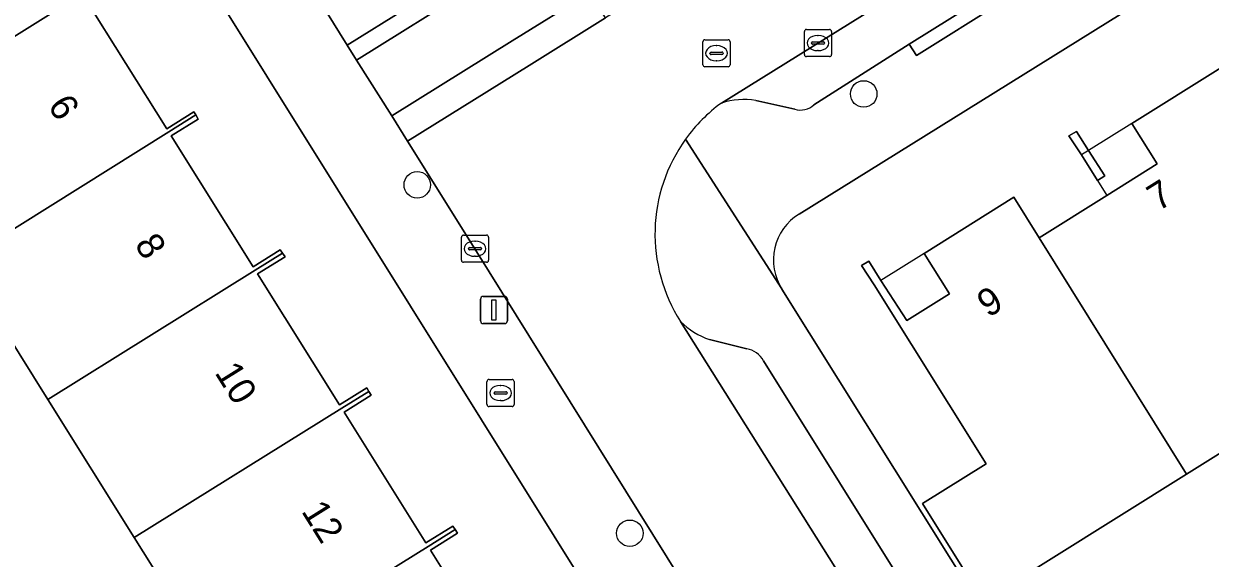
# Model space of a CAD drawing. Extents: x 158835 to 160077, y 386387 to 387778.
# Drawn here: x 159103.26 to 159146.99, y 387136.96 to 387156.67 of the extents above; entities that cross this region are included whole.
import ezdxf

# ---------------------------------------------------------------- set-up
doc = ezdxf.new("R2010")
doc.units = 0
for name, color, linetype in [('IMGEO_Boom', 7, 'Continuous'), ('IMGEO_Brandkraan', 7, 'Continuous'), ('IMGEO_Erf', 7, 'Continuous'), ('IMGEO_Kolk', 7, 'Continuous'), ('IMGEO_Lichtmast', 7, 'Continuous'), ('IMGEO_Pand', 7, 'Continuous'), ('IMGEO_Pand_nummerreeks', 7, 'Continuous'), ('IMGEO_Pand_overbouw', 7, 'Continuous'), ('IMGEO_Parkeervlak_open', 7, 'Continuous'), ('IMGEO_Rijbaan_lokaal_open', 7, 'Continuous'), ('IMGEO_Rioolput', 7, 'Continuous'), ('IMGEO_Voetpad_open', 7, 'Continuous')]:
    doc.layers.add(name, color=color, linetype=linetype)

msp = doc.modelspace()

# ---------------------------------------------------------------- linework, layer by layer
at = {"layer": 'IMGEO_Boom'}
for centre in [(159134.213, 387154.078), (159117.763, 387150.726), (159125.594, 387137.881)]:
    msp.add_circle(centre, 0.489, dxfattribs=at)
at = {"layer": 'IMGEO_Brandkraan'}
for p, q in [((159120.332, 387142.626), (159120.332, 387143.478)), ((159120.407, 387143.552), (159121.259, 387143.552)), ((159120.82, 387143.332), (159120.845, 387143.332)), ((159121.333, 387143.478), (159121.333, 387142.626)), ((159120.591, 387143.046), (159120.591, 387143.058)), ((159121.029, 387143.009), (159120.631, 387143.009)), ((159120.634, 387143.095), (159121.032, 387143.095)), ((159120.843, 387142.772), (159120.818, 387142.772)), ((159121.075, 387143.058), (159121.075, 387143.046)), ((159121.259, 387142.552), (159120.407, 387142.552))]:
    msp.add_line(p, q, dxfattribs=at)
for points in [[(159120.332, 387142.626), (159120.332, 387143.478)], [(159120.407, 387143.552), (159121.259, 387143.552)], [(159121.333, 387143.478), (159121.333, 387142.626)], [(159121.259, 387142.552), (159120.407, 387142.552)]]:
    msp.add_lwpolyline(points, dxfattribs=at)
for centre, radius, start, end in [((159120.409, 387143.476), 0.0765, 91.552, 178.448), ((159120.409, 387143.476), 0.0765, 91.552, 178.448), ((159121.257, 387143.476), 0.0765, 1.552, 88.448), ((159121.257, 387143.476), 0.0765, 1.552, 88.448), ((159120.631, 387143.055), 0.0403, 85.8775, 175.7526), ((159120.628, 387143.045), 0.0366, 178.938, 274.7102), ((159121.032, 387143.052), 0.043, 264.8664, 352.4533), ((159121.036, 387143.057), 0.0386, 1.7309, 96.639), ((159120.409, 387142.628), 0.0765, 181.552, 268.448), ((159120.409, 387142.628), 0.0765, 181.552, 268.448), ((159121.257, 387142.628), 0.0765, 271.552, 358.448), ((159121.257, 387142.628), 0.0765, 271.552, 358.448)]:
    msp.add_arc(centre, radius, start, end, dxfattribs=at)
for centre, major_axis, ratio, start_param, end_param in [((159120.819, 387143.052), (-0.387, 0.002), 0.722429, 4.712389, 7.853982), ((159120.844, 387143.052), (-0.39, 0.002), 0.717154, 1.570796, 4.712389)]:
    msp.add_ellipse(centre, major_axis=major_axis, ratio=ratio, start_param=start_param, end_param=end_param, dxfattribs=at)
at = {"layer": 'IMGEO_Erf'}
for points in [[(159192.812, 387154.528), (159184.858, 387169.495), (159180.565, 387177.574), (159180.465, 387177.724), (159180.352, 387177.865), (159180.227, 387177.995), (159180.091, 387178.113), (159179.944, 387178.219), (159179.789, 387178.311), (159179.627, 387178.389), (159179.458, 387178.452), (159179.284, 387178.5), (159179.106, 387178.532), (159178.926, 387178.548), (159178.746, 387178.548), (159178.566, 387178.532), (159178.388, 387178.5), (159178.214, 387178.452), (159178.045, 387178.389), (159177.883, 387178.311), (159177.794, 387178.26), (159131.832, 387149.649)], [(159128.1, 387129.289), (159098.935, 387175.998)], [(159105.515, 387157.619), (159108.532, 387152.795), (159109.533, 387153.421), (159109.601, 387153.308), (159109.693, 387153.153), (159108.697, 387152.53), (159111.713, 387147.708), (159112.714, 387148.334), (159112.799, 387148.209), (159112.89, 387148.073), (159111.879, 387147.441), (159114.899, 387142.611), (159115.903, 387143.239), (159115.98, 387143.113), (159116.067, 387142.972), (159115.065, 387142.346), (159118.079, 387137.527), (159119.072, 387138.148), (159119.159, 387138.018), (159119.247, 387137.885), (159118.246, 387137.259), (159121.256, 387132.446)], [(159153.734, 387144.832), (159146.108, 387140.062), (159138.627, 387135.383), (159136.383, 387138.973), (159138.73, 387140.444), (159134.594, 387147.043), (159134.13, 387147.748), (159134.4, 387147.914), (159134.847, 387147.201), (159135.801, 387145.722), (159137.374, 387146.707), (159136.44, 387148.199), (159139.747, 387150.271), (159140.678, 387148.777), (159143.174, 387150.339), (159145.023, 387151.496), (159144.089, 387152.989), (159147.369, 387155.042)], [(159102.591, 387130.021), (159103.629, 387128.333), (159102.891, 387127.877), (159105.538, 387123.606), (159102.83, 387121.872), (159104.491, 387119.253), (159107.123, 387120.891), (159109.245, 387117.494), (159116.968, 387122.325), (159113.699, 387127.551), (159110.519, 387132.633), (159107.334, 387137.724), (159104.149, 387142.815), (159100.965, 387147.905)], [(159131.202, 387146.887), (159138.432, 387135.312), (159143.549, 387127.119), (159158.165, 387103.724), (159222.278, 387001.075)]]:
    msp.add_lwpolyline(points, dxfattribs=at)
msp.add_lwpolyline([(159143.102, 387151.057), (159142.831, 387150.887), (159142.24, 387151.831), (159141.777, 387152.54), (159142.052, 387152.699), (159142.495, 387151.991)], close=True, dxfattribs=at)
msp.add_arc((159132.858, 387147.962), 1.974, 121.3088, 212.993, dxfattribs=at)
at = {"layer": 'IMGEO_Kolk'}
for p, q in [((159132.028, 387155.529), (159132.028, 387156.381)), ((159132.103, 387156.455), (159132.955, 387156.455)), ((159133.029, 387156.381), (159133.029, 387155.529)), ((159132.287, 387155.949), (159132.287, 387155.961)), ((159132.725, 387155.912), (159132.327, 387155.912)), ((159132.33, 387155.998), (159132.728, 387155.998)), ((159132.516, 387156.235), (159132.541, 387156.235)), ((159132.771, 387155.961), (159132.771, 387155.949)), ((159132.955, 387155.455), (159132.103, 387155.455)), ((159132.539, 387155.675), (159132.514, 387155.675)), ((159119.465, 387148.872), (159120.317, 387148.872)), ((159119.39, 387147.946), (159119.39, 387148.798)), ((159119.692, 387148.415), (159120.09, 387148.415)), ((159119.878, 387148.652), (159119.903, 387148.652)), ((159120.391, 387148.798), (159120.391, 387147.946)), ((159119.649, 387148.366), (159119.649, 387148.378)), ((159120.087, 387148.329), (159119.689, 387148.329)), ((159119.901, 387148.092), (159119.876, 387148.092)), ((159120.133, 387148.378), (159120.133, 387148.366)), ((159120.317, 387147.872), (159119.465, 387147.872))]:
    msp.add_line(p, q, dxfattribs=at)
for points in [[(159132.028, 387155.529), (159132.028, 387156.381)], [(159132.103, 387156.455), (159132.955, 387156.455)], [(159133.029, 387156.381), (159133.029, 387155.529)], [(159132.955, 387155.455), (159132.103, 387155.455)], [(159119.465, 387148.872), (159120.317, 387148.872)], [(159119.39, 387147.946), (159119.39, 387148.798)], [(159120.391, 387148.798), (159120.391, 387147.946)], [(159120.317, 387147.872), (159119.465, 387147.872)]]:
    msp.add_lwpolyline(points, dxfattribs=at)
for centre, radius, start, end in [((159132.105, 387156.379), 0.0765, 91.552, 178.448), ((159132.105, 387156.379), 0.0765, 91.552, 178.448), ((159132.953, 387156.379), 0.0765, 1.552, 88.448), ((159132.953, 387156.379), 0.0765, 1.552, 88.448), ((159132.327, 387155.958), 0.0403, 85.8775, 175.7526), ((159132.324, 387155.948), 0.0366, 178.938, 274.7102), ((159132.728, 387155.955), 0.043, 264.8664, 352.4533), ((159132.732, 387155.96), 0.0386, 1.7309, 96.639), ((159132.105, 387155.531), 0.0765, 181.552, 268.448), ((159132.105, 387155.531), 0.0765, 181.552, 268.448), ((159132.953, 387155.531), 0.0765, 271.552, 358.448), ((159132.953, 387155.531), 0.0765, 271.552, 358.448), ((159119.467, 387148.796), 0.0765, 91.552, 178.448), ((159119.467, 387148.796), 0.0765, 91.552, 178.448), ((159120.315, 387148.796), 0.0765, 1.552, 88.448), ((159120.315, 387148.796), 0.0765, 1.552, 88.448), ((159119.689, 387148.375), 0.0403, 85.8775, 175.7526), ((159120.094, 387148.377), 0.0386, 1.7309, 96.639), ((159119.467, 387147.948), 0.0765, 181.552, 268.448), ((159119.467, 387147.948), 0.0765, 181.552, 268.448), ((159119.686, 387148.365), 0.0366, 178.938, 274.7102), ((159120.09, 387148.372), 0.043, 264.8664, 352.4533), ((159120.315, 387147.948), 0.0765, 271.552, 358.448), ((159120.315, 387147.948), 0.0765, 271.552, 358.448)]:
    msp.add_arc(centre, radius, start, end, dxfattribs=at)
for centre, major_axis, ratio, start_param, end_param in [((159132.515, 387155.955), (-0.387, 0.002), 0.722429, 4.712389, 7.853982), ((159132.54, 387155.955), (-0.39, 0.002), 0.717154, 1.570796, 4.712389), ((159119.877, 387148.372), (-0.387, 0.002), 0.722429, 4.712389, 7.853982), ((159119.902, 387148.372), (-0.39, 0.002), 0.717154, 1.570796, 4.712389)]:
    msp.add_ellipse(centre, major_axis=major_axis, ratio=ratio, start_param=start_param, end_param=end_param, dxfattribs=at)
at = {"layer": 'IMGEO_Lichtmast'}
for p, q in [((159120.094, 387145.713), (159120.094, 387146.513)), ((159120.094, 387146.513), (159120.094, 387145.713)), ((159120.194, 387146.613), (159120.984, 387146.613)), ((159120.984, 387146.613), (159120.194, 387146.613)), ((159121.084, 387146.513), (159121.084, 387145.713)), ((159121.084, 387145.713), (159121.084, 387146.513)), ((159120.984, 387145.613), (159120.194, 387145.613)), ((159120.194, 387145.613), (159120.984, 387145.613))]:
    msp.add_line(p, q, dxfattribs=at)
msp.add_lwpolyline([(159120.514, 387146.488), (159120.664, 387146.488), (159120.664, 387145.738), (159120.514, 387145.738), (159120.514, 387146.488)], dxfattribs=at)
for centre, start, end in [((159120.194, 387146.513), 90, 180), ((159120.194, 387146.513), 90, 180), ((159120.984, 387146.513), 0, 90), ((159120.984, 387146.513), 360, 90), ((159120.194, 387145.713), 180, 270), ((159120.194, 387145.713), 180, 270), ((159120.984, 387145.713), 270, 0), ((159120.984, 387145.713), 270, 0)]:
    msp.add_arc(centre, 0.1, start, end, dxfattribs=at)
at = {"layer": 'IMGEO_Pand'}
for points in [[(159102.237, 387162.861), (159094.601, 387158.079), (159097.78, 387152.996), (159105.417, 387157.775), (159106.421, 387158.403), (159106.353, 387158.513), (159105.348, 387157.885), (159102.329, 387162.713), (159103.328, 387163.337), (159103.238, 387163.488)], [(159109.601, 387153.308), (159109.533, 387153.421), (159108.532, 387152.795), (159105.515, 387157.619), (159106.518, 387158.246), (159106.421, 387158.403), (159105.417, 387157.775), (159097.78, 387152.996), (159100.965, 387147.905), (159108.602, 387152.683)], [(159148.301, 387153.547), (159147.369, 387155.042), (159144.089, 387152.989), (159145.023, 387151.496), (159143.174, 387150.339), (159140.678, 387148.777), (159146.108, 387140.062), (159153.734, 387144.832)], [(159108.602, 387152.683), (159100.965, 387147.905), (159104.149, 387142.815), (159111.792, 387147.581), (159112.799, 387148.209), (159112.714, 387148.334), (159111.713, 387147.708), (159108.697, 387152.53), (159109.693, 387153.153), (159109.601, 387153.308)], [(159142.495, 387151.991), (159142.052, 387152.699), (159141.777, 387152.54), (159142.24, 387151.831), (159142.831, 387150.887), (159143.102, 387151.057)], [(159140.678, 387148.777), (159139.747, 387150.271), (159136.44, 387148.199), (159137.374, 387146.707), (159135.801, 387145.722), (159134.847, 387147.201), (159134.4, 387147.914), (159134.13, 387147.748), (159134.594, 387147.043), (159138.73, 387140.444), (159136.383, 387138.973), (159138.627, 387135.383), (159146.108, 387140.062)], [(159115.98, 387143.113), (159115.903, 387143.239), (159114.899, 387142.611), (159111.879, 387147.441), (159112.89, 387148.073), (159112.799, 387148.209), (159111.792, 387147.581), (159104.149, 387142.815), (159107.334, 387137.724), (159114.977, 387142.488)], [(159114.977, 387142.488), (159107.334, 387137.724), (159110.519, 387132.633), (159118.161, 387137.396), (159119.159, 387138.018), (159119.072, 387138.148), (159118.079, 387137.527), (159115.065, 387142.346), (159116.067, 387142.972), (159115.98, 387143.113)], [(159118.161, 387137.396), (159110.519, 387132.633), (159113.699, 387127.551), (159121.33, 387132.328), (159122.332, 387132.955), (159122.258, 387133.072), (159121.256, 387132.446), (159118.246, 387137.259), (159119.247, 387137.885), (159119.159, 387138.018)]]:
    msp.add_lwpolyline(points, close=True, dxfattribs=at)
at = {"layer": 'IMGEO_Pand_overbouw'}
for points in [[(159142.495, 387151.991), (159142.24, 387151.831), (159142.831, 387150.887), (159143.174, 387150.339), (159145.023, 387151.496), (159144.089, 387152.989)], [(159134.847, 387147.201), (159135.801, 387145.722), (159137.374, 387146.707), (159136.44, 387148.199)]]:
    msp.add_lwpolyline(points, close=True, dxfattribs=at)
at = {"layer": 'IMGEO_Parkeervlak_open'}
for points in [[(159176.063, 387183.08), (159170.211, 387179.417), (159151.418, 387167.712), (159128.969, 387153.744)], [(159132.379, 387153.68), (159135.892, 387155.914), (159139.082, 387157.916), (159143.344, 387160.566), (159146.528, 387162.551), (159151.219, 387165.464), (159154.416, 387167.461)], [(159130.234, 387153.84), (159131.674, 387153.519)], [(159127.465, 387145.688), (159134.862, 387133.929), (159140.143, 387125.45), (159141.666, 387126.399)], [(159129.909, 387144.687), (159128.536, 387145.027)], [(159141.666, 387126.399), (159130.521, 387144.242)]]:
    msp.add_lwpolyline(points, dxfattribs=at)
for centre, radius, start, end in [((159129.802, 387151.146), 2.729, 80.8973, 107.7824), ((159131.891, 387154.193), 0.708, 252.1438, 313.5842), ((159129.334, 387147.518), 2.616, 224.3981, 252.2378), ((159129.711, 387143.771), 0.937, 30.1554, 77.801)]:
    msp.add_arc(centre, radius, start, end, dxfattribs=at)
at = {"layer": 'IMGEO_Rijbaan_lokaal_open'}
for points in [[(159186.985, 387195.824), (159182.901, 387193.183), (159182.797, 387193.116), (159182.679, 387193.04), (159174.039, 387187.668), (159173.315, 387187.218), (159173.218, 387187.157), (159168.759, 387184.361), (159149.771, 387172.508), (159129.852, 387160.089), (159124.698, 387156.88), (159121.887, 387155.13), (159117.406, 387152.34), (159119.888, 387148.372), (159130.485, 387131.344), (159141.225, 387114.195), (159142.231, 387112.577), (159142.423, 387112.239), (159142.602, 387111.89)], [(159128.969, 387153.744), (159151.418, 387167.712), (159170.211, 387179.417), (159176.063, 387183.08), (159176.9, 387183.614), (159185.441, 387188.891)], [(159145.475, 387101.632), (159152.358, 387105.91), (159148.492, 387112.077), (159146.487, 387115.275), (159145.363, 387117.069), (159143.728, 387119.694), (159140.143, 387125.45), (159134.862, 387133.929), (159127.465, 387145.688)]]:
    msp.add_lwpolyline(points, dxfattribs=at)
for points in [[(159102.608, 387185.676), (159100.153, 387189.591), (159095.851, 387186.92), (159101.246, 387178.309), (159109.051, 387165.756), (159115.179, 387155.878), (159119.526, 387158.595), (159113.156, 387168.75)], [(159119.526, 387158.595), (159115.179, 387155.878), (159115.522, 387155.326), (159119.859, 387158.041), (159119.689, 387158.285), (159119.584, 387158.484)]]:
    msp.add_lwpolyline(points, close=True, dxfattribs=at)
for centre, radius, start, end in [((159132.505, 387148.924), 5.978, 126.264, 144.2561), ((159132.517, 387148.913), 5.994, 144.2415, 212.5573)]:
    msp.add_arc(centre, radius, start, end, dxfattribs=at)
at = {"layer": 'IMGEO_Rioolput'}
for p, q in [((159128.29, 387155.153), (159128.29, 387156.005)), ((159128.365, 387156.079), (159129.217, 387156.079)), ((159128.778, 387155.859), (159128.803, 387155.859)), ((159129.291, 387156.005), (159129.291, 387155.153)), ((159128.549, 387155.573), (159128.549, 387155.585)), ((159128.987, 387155.536), (159128.589, 387155.536)), ((159128.592, 387155.622), (159128.99, 387155.622)), ((159129.033, 387155.585), (159129.033, 387155.573)), ((159129.217, 387155.079), (159128.365, 387155.079)), ((159128.801, 387155.299), (159128.776, 387155.299))]:
    msp.add_line(p, q, dxfattribs=at)
for points in [[(159128.29, 387155.153), (159128.29, 387156.005)], [(159128.365, 387156.079), (159129.217, 387156.079)], [(159129.291, 387156.005), (159129.291, 387155.153)], [(159129.217, 387155.079), (159128.365, 387155.079)]]:
    msp.add_lwpolyline(points, dxfattribs=at)
for centre, radius, start, end in [((159128.367, 387156.003), 0.0765, 91.552, 178.448), ((159128.367, 387156.003), 0.0765, 91.552, 178.448), ((159129.215, 387156.003), 0.0765, 1.552, 88.448), ((159129.215, 387156.003), 0.0765, 1.552, 88.448), ((159128.589, 387155.582), 0.0403, 85.8775, 175.7526), ((159128.586, 387155.572), 0.0366, 178.938, 274.7102), ((159128.99, 387155.579), 0.043, 264.8664, 352.4533), ((159128.994, 387155.584), 0.0386, 1.7309, 96.639), ((159128.367, 387155.155), 0.0765, 181.552, 268.448), ((159128.367, 387155.155), 0.0765, 181.552, 268.448), ((159129.215, 387155.155), 0.0765, 271.552, 358.448), ((159129.215, 387155.155), 0.0765, 271.552, 358.448)]:
    msp.add_arc(centre, radius, start, end, dxfattribs=at)
for centre, major_axis, ratio, start_param, end_param in [((159128.777, 387155.579), (-0.387, 0.002), 0.722429, 4.712389, 7.853982), ((159128.802, 387155.579), (-0.39, 0.002), 0.717154, 1.570796, 4.712389)]:
    msp.add_ellipse(centre, major_axis=major_axis, ratio=ratio, start_param=start_param, end_param=end_param, dxfattribs=at)
at = {"layer": 'IMGEO_Voetpad_open'}
for points in [[(159096.051, 387180.526), (159098.894, 387176.097), (159098.935, 387175.998), (159128.1, 387129.289), (159128.897, 387128.013), (159128.914, 387127.985), (159134.38, 387119.23), (159135.688, 387117.136), (159138.894, 387112.002), (159140.608, 387109.256)], [(159174.403, 387179.897), (159169.734, 387176.991), (159169.998, 387176.567), (159166.805, 387174.574), (159166.541, 387174.998), (159161.863, 387172.098), (159162.127, 387171.674), (159158.931, 387169.68), (159158.667, 387170.104), (159154.416, 387167.461), (159154.68, 387167.037), (159151.483, 387165.04), (159151.219, 387165.464), (159146.528, 387162.551), (159146.792, 387162.127), (159143.608, 387160.142), (159143.344, 387160.566), (159139.082, 387157.916), (159139.347, 387157.493), (159136.157, 387155.491), (159135.892, 387155.914), (159132.379, 387153.68)], [(159119.888, 387148.372), (159117.406, 387152.34), (159116.825, 387153.274), (159115.522, 387155.326), (159115.179, 387155.878), (159109.051, 387165.756), (159101.246, 387178.309)], [(159131.832, 387149.649), (159177.794, 387178.26)], [(159119.859, 387158.041), (159115.522, 387155.326), (159116.825, 387153.274), (159121.257, 387156.034), (159124.117, 387157.814)], [(159131.674, 387153.519), (159130.234, 387153.84)], [(159127.653, 387152.416), (159131.196, 387146.888), (159131.202, 387146.887)], [(159158.165, 387103.724), (159143.549, 387127.119), (159138.432, 387135.312), (159131.202, 387146.887), (159131.196, 387146.888), (159127.653, 387152.416)], [(159142.602, 387111.89), (159142.423, 387112.239), (159142.231, 387112.577), (159141.225, 387114.195), (159130.485, 387131.344), (159119.888, 387148.372)], [(159128.536, 387145.027), (159129.909, 387144.687)], [(159130.521, 387144.242), (159141.666, 387126.399), (159145.253, 387120.644), (159148.034, 387116.241), (159150.042, 387113.049), (159152.323, 387109.35)]]:
    msp.add_lwpolyline(points, dxfattribs=at)
for points in [[(159121.887, 387155.13), (159124.698, 387156.88), (159124.117, 387157.814), (159121.257, 387156.034), (159116.825, 387153.274), (159117.406, 387152.34)], [(159139.082, 387157.916), (159135.892, 387155.914), (159136.157, 387155.491), (159139.347, 387157.493)]]:
    msp.add_lwpolyline(points, close=True, dxfattribs=at)
for centre, radius, start, end in [((159132.505, 387148.924), 5.978, 126.264, 144.2561), ((159129.802, 387151.146), 2.729, 80.8973, 107.7824), ((159131.891, 387154.193), 0.708, 252.1438, 313.5842), ((159132.517, 387148.913), 5.994, 144.2415, 212.5573), ((159132.858, 387147.962), 1.974, 121.3088, 212.993), ((159129.334, 387147.518), 2.616, 224.3981, 252.2378), ((159129.711, 387143.771), 0.937, 30.1554, 77.801)]:
    msp.add_arc(centre, radius, start, end, dxfattribs=at)

# ---------------------------------------------------------------- texts
at = {"layer": 'IMGEO_Pand_nummerreeks'}
for s, rotation, p in [('6', 302.0025, (159104.124, 387153.65)), ('7', 32.0398, (159145.069, 387149.732)), ('8', 302.0025, (159107.323, 387148.53)), ('9', 32.0684, (159138.805, 387145.81)), ('10', 302.0025, (159110.276, 387143.804)), ('12', 302.0025, (159113.471, 387138.693))]:
    msp.add_text(s, height=1, rotation=rotation, dxfattribs=at).set_placement(p)

doc.saveas('drawing.dxf')
